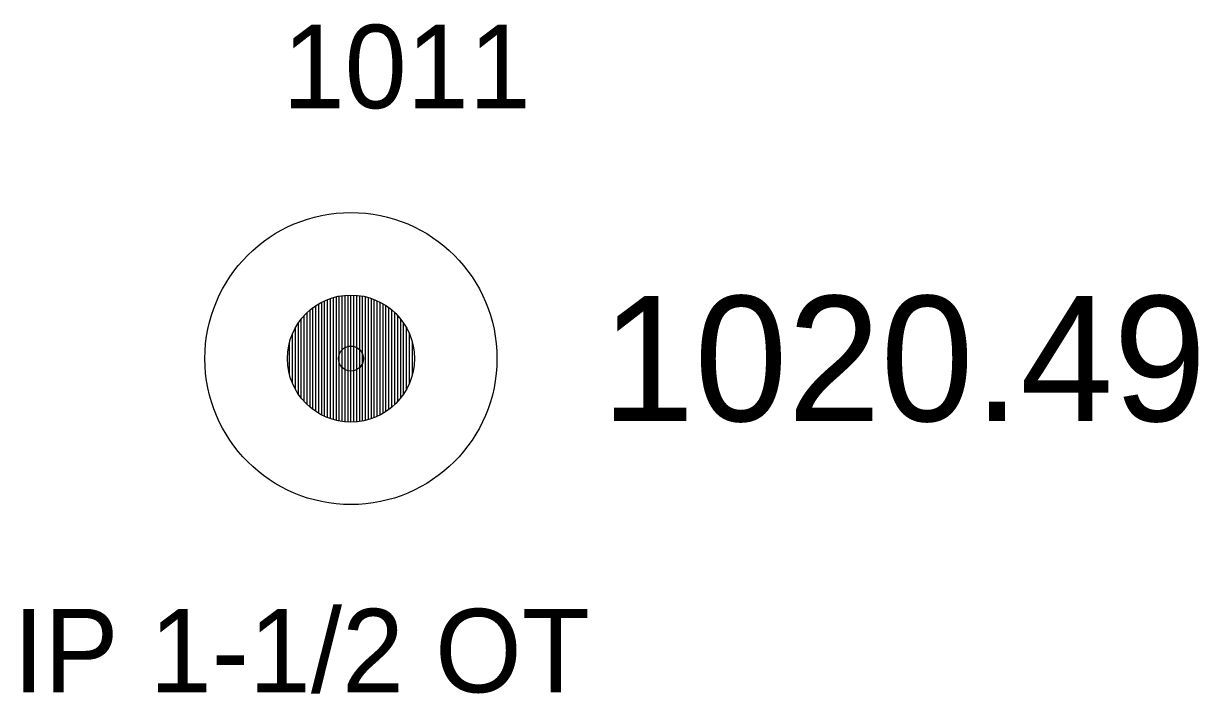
# Model space of a CAD drawing. Extents: x 1578957 to 1581675, y 1115963 to 1120391.
# Drawn here: x 1579076.43 to 1579090.51, y 1117515.85 to 1117523.88 of the extents above; entities that cross this region are included whole.
import ezdxf

# ---------------------------------------------------------------- set-up
doc = ezdxf.new("R2010")
doc.units = 0
for name, color, linetype in [('RD_EX_DV_Prop_txCode', 7, 'Continuous'), ('RD_EX_DV_PropPin', 7, 'Continuous'), ('RD_EX_TX_DV_Prop_ELEV', 7, 'Continuous'), ('RD_SMD_Locator', 7, 'Continuous')]:
    doc.layers.add(name, color=color, linetype=linetype)

msp = doc.modelspace()

# ---------------------------------------------------------------- linework, layer by layer
at = {"layer": 'RD_EX_DV_PropPin'}
for p, q in [((1579080.043, 1117519.167), (1579080.043, 1117520.553)), ((1579080.078, 1117519.153), (1579080.078, 1117520.568)), ((1579080.113, 1117519.14), (1579080.113, 1117520.581)), ((1579080.148, 1117519.129), (1579080.148, 1117520.592)), ((1579080.183, 1117519.12), (1579080.183, 1117520.601)), ((1579080.218, 1117519.112), (1579080.218, 1117520.608)), ((1579080.253, 1117519.106), (1579080.253, 1117520.614)), ((1579080.288, 1117519.102), (1579080.288, 1117520.618)), ((1579080.323, 1117519.1), (1579080.323, 1117520.62)), ((1579080.358, 1117519.099), (1579080.358, 1117520.621)), ((1579080.393, 1117519.1), (1579080.393, 1117520.62)), ((1579080.428, 1117519.102), (1579080.428, 1117520.618)), ((1579080.463, 1117519.106), (1579080.463, 1117520.614)), ((1579080.498, 1117519.112), (1579080.498, 1117520.608)), ((1579080.533, 1117519.12), (1579080.533, 1117520.601)), ((1579080.568, 1117519.129), (1579080.568, 1117520.592)), ((1579080.603, 1117519.14), (1579080.603, 1117520.581)), ((1579080.638, 1117519.153), (1579080.638, 1117520.568)), ((1579080.673, 1117519.167), (1579080.673, 1117520.553)), ((1579079.833, 1117519.309), (1579079.833, 1117520.411)), ((1579079.868, 1117519.278), (1579079.868, 1117520.442)), ((1579079.903, 1117519.25), (1579079.903, 1117520.47)), ((1579079.938, 1117519.226), (1579079.938, 1117520.495)), ((1579079.973, 1117519.204), (1579079.973, 1117520.517)), ((1579080.008, 1117519.185), (1579080.008, 1117520.536)), ((1579080.708, 1117519.185), (1579080.708, 1117520.536)), ((1579080.743, 1117519.204), (1579080.743, 1117520.517)), ((1579080.778, 1117519.226), (1579080.778, 1117520.495)), ((1579080.813, 1117519.25), (1579080.813, 1117520.47)), ((1579080.848, 1117519.278), (1579080.848, 1117520.442)), ((1579080.883, 1117519.309), (1579080.883, 1117520.411)), ((1579079.728, 1117519.434), (1579079.728, 1117520.287)), ((1579079.763, 1117519.386), (1579079.763, 1117520.334)), ((1579079.798, 1117519.345), (1579079.798, 1117520.375)), ((1579080.919, 1117519.345), (1579080.919, 1117520.375)), ((1579080.954, 1117519.386), (1579080.954, 1117520.334)), ((1579080.989, 1117519.434), (1579080.989, 1117520.287)), ((1579079.658, 1117519.562), (1579079.658, 1117520.158)), ((1579079.693, 1117519.491), (1579079.693, 1117520.23)), ((1579081.024, 1117519.491), (1579081.024, 1117520.23)), ((1579081.059, 1117519.562), (1579081.059, 1117520.158)), ((1579079.623, 1117519.664), (1579079.623, 1117520.056)), ((1579081.094, 1117519.664), (1579081.094, 1117520.056))]:
    msp.add_line(p, q, dxfattribs=at)
for radius in [1.75, 0.761]:
    msp.add_circle((1579080.358, 1117519.86), radius, dxfattribs=at)
at = {"layer": 'RD_SMD_Locator'}
msp.add_circle((1579080.358, 1117519.86), 0.15, dxfattribs=at)

# ---------------------------------------------------------------- texts
at = {"layer": 'RD_EX_DV_Prop_txCode'}
for s, p in [('1011', (1579079.539, 1117522.86)), ('IP 1-1/2 OT', (1579076.311, 1117515.86))]:
    msp.add_text(s, height=1, dxfattribs=at).set_placement(p)
at = {"layer": 'RD_EX_TX_DV_Prop_ELEV'}
msp.add_text('1020.49', height=1.5, dxfattribs=at).set_placement((1579083.358, 1117519.11))

doc.saveas('drawing.dxf')
